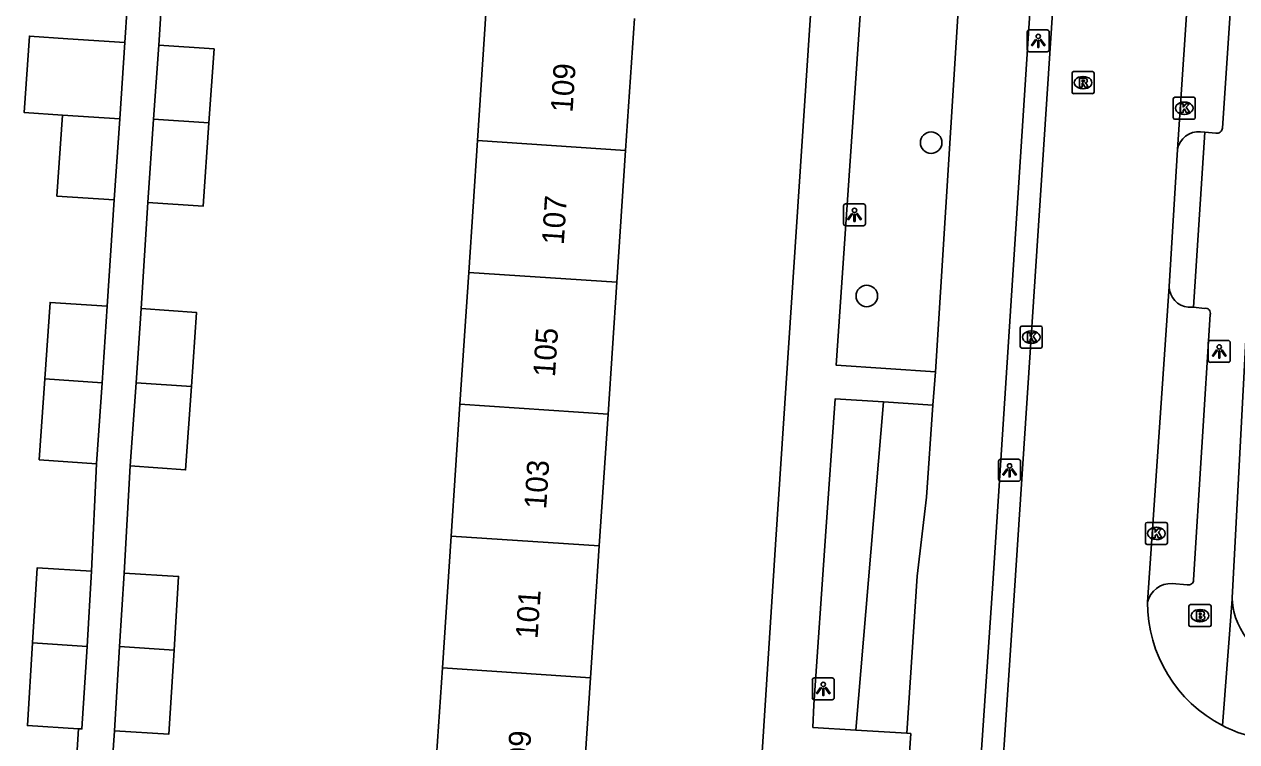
# Model space of a CAD drawing. Extents: x 161848 to 162726, y 385382 to 386521.
# Drawn here: x 162001.6 to 162056.7, y 386169.2 to 386201.9 of the extents above; entities that cross this region are included whole.
import ezdxf

# ---------------------------------------------------------------- set-up
doc = ezdxf.new("R2010")
doc.units = 0
for name, color, linetype in [('IMGEO_Boom', 7, 'Continuous'), ('IMGEO_Brandkraan', 7, 'Continuous'), ('IMGEO_Fietspad_gesloten', 7, 'Continuous'), ('IMGEO_Groenvoorziening', 7, 'Continuous'), ('IMGEO_Kolk', 7, 'Continuous'), ('IMGEO_Lichtpunt', 7, 'Continuous'), ('IMGEO_Pand', 7, 'Continuous'), ('IMGEO_Pand_nummerreeks', 7, 'Continuous'), ('IMGEO_Rijbaan_lokaal_open', 7, 'Continuous'), ('IMGEO_Rioolput', 7, 'Continuous'), ('IMGEO_Voetpad_open', 7, 'Continuous')]:
    doc.layers.add(name, color=color, linetype=linetype)

msp = doc.modelspace()

# ---------------------------------------------------------------- linework, layer by layer
at = {"layer": 'IMGEO_Boom'}
for centre in [(162042.788, 386196.471), (162039.863, 386189.5)]:
    msp.add_circle(centre, 0.489, dxfattribs=at)
at = {"layer": 'IMGEO_Brandkraan'}
for p, q in [((162054.513, 386174.544), (162054.513, 386175.396)), ((162054.588, 386175.47), (162055.44, 386175.47)), ((162055.001, 386175.25), (162055.026, 386175.25)), ((162055.514, 386175.396), (162055.514, 386174.544)), ((162055.44, 386174.47), (162054.588, 386174.47)), ((162055.024, 386174.69), (162054.999, 386174.69))]:
    msp.add_line(p, q, dxfattribs=at)
for points in [[(162054.513, 386174.544), (162054.513, 386175.396)], [(162054.588, 386175.47), (162055.44, 386175.47)], [(162055.514, 386175.396), (162055.514, 386174.544)], [(162054.861, 386175.17), (162054.861, 386174.77), (162055.074, 386174.77)], [(162055.092, 386175.17), (162054.861, 386175.17)], [(162055.04, 386175.089), (162054.986, 386175.089), (162054.986, 386175.013)], [(162054.986, 386175.013), (162055.039, 386175.013)], [(162055.048, 386174.937), (162054.986, 386174.937), (162054.986, 386174.856)], [(162054.986, 386174.856), (162055.048, 386174.856)], [(162055.44, 386174.47), (162054.588, 386174.47)]]:
    msp.add_lwpolyline(points, dxfattribs=at)
for centre, radius, start, end in [((162054.59, 386175.394), 0.0765, 91.552, 178.448), ((162054.59, 386175.394), 0.0765, 91.552, 178.448), ((162055.438, 386175.394), 0.0765, 1.552, 88.448), ((162055.438, 386175.394), 0.0765, 1.552, 88.448), ((162055.041, 386175.051), 0.0379, 267.8285, 90.9355), ((162055.049, 386174.896), 0.0404, 269.8759, 90.5077), ((162055.08, 386175.021), 0.251, 268.6676, 293.5347), ((162055.096, 386175.025), 0.145, 59.4692, 91.5367), ((162055.121, 386175.072), 0.0922, 285.5137, 58.1501), ((162055.126, 386174.88), 0.105, 301.3115, 78.989), ((162054.59, 386174.546), 0.0765, 181.552, 268.448), ((162054.59, 386174.546), 0.0765, 181.552, 268.448), ((162055.438, 386174.546), 0.0765, 271.552, 358.448), ((162055.438, 386174.546), 0.0765, 271.552, 358.448)]:
    msp.add_arc(centre, radius, start, end, dxfattribs=at)
for centre, major_axis, ratio, start_param, end_param in [((162055, 386174.97), (-0.387, 0.002), 0.722429, 4.712389, 7.853982), ((162055.025, 386174.97), (-0.39, 0.002), 0.717154, 1.570796, 4.712389)]:
    msp.add_ellipse(centre, major_axis=major_axis, ratio=ratio, start_param=start_param, end_param=end_param, dxfattribs=at)
at = {"layer": 'IMGEO_Fietspad_gesloten'}
for points in [[(162044.994, 386167.532), (162045.595, 386176.434), (162048.664, 386223.883)], [(162044.15, 386204.652), (162042.986, 386186.047)], [(162042.986, 386186.047), (162042.865, 386184.541)], [(162042.865, 386184.541), (162042.584, 386180.361), (162042.155, 386176.763), (162041.688, 386169.621)], [(162041.688, 386169.621), (162041.864, 386169.606), (162041.762, 386168.083)]]:
    msp.add_lwpolyline(points, dxfattribs=at)
at = {"layer": 'IMGEO_Groenvoorziening'}
msp.add_lwpolyline([(162039.359, 386169.769), (162040.628, 386184.681)], dxfattribs=at)
at = {"layer": 'IMGEO_Kolk'}
for p, q in [((162053.799, 386197.609), (162053.799, 386198.461)), ((162053.874, 386198.535), (162054.726, 386198.535)), ((162054.8, 386198.461), (162054.8, 386197.609)), ((162054.287, 386198.315), (162054.312, 386198.315)), ((162054.726, 386197.535), (162053.874, 386197.535)), ((162054.31, 386197.755), (162054.285, 386197.755)), ((162046.842, 386187.204), (162046.842, 386188.056)), ((162046.917, 386188.13), (162047.769, 386188.13)), ((162047.843, 386188.056), (162047.843, 386187.204)), ((162047.33, 386187.91), (162047.355, 386187.91)), ((162047.769, 386187.13), (162046.917, 386187.13)), ((162047.353, 386187.35), (162047.328, 386187.35)), ((162052.529, 386178.282), (162052.529, 386179.134)), ((162052.604, 386179.208), (162053.456, 386179.208)), ((162053.53, 386179.134), (162053.53, 386178.282)), ((162053.017, 386178.988), (162053.042, 386178.988)), ((162053.456, 386178.208), (162052.604, 386178.208)), ((162053.04, 386178.428), (162053.015, 386178.428))]:
    msp.add_line(p, q, dxfattribs=at)
for points in [[(162053.799, 386197.609), (162053.799, 386198.461)], [(162053.874, 386198.535), (162054.726, 386198.535)], [(162054.8, 386198.461), (162054.8, 386197.609)], [(162054.12, 386198.235), (162054.243, 386198.235), (162054.243, 386198.084), (162054.373, 386198.235), (162054.537, 386198.235), (162054.391, 386198.084), (162054.544, 386197.835), (162054.392, 386197.835), (162054.307, 386197.999), (162054.243, 386197.932), (162054.243, 386197.835), (162054.12, 386197.835), (162054.12, 386198.235)], [(162054.726, 386197.535), (162053.874, 386197.535)], [(162046.842, 386187.204), (162046.842, 386188.056)], [(162046.917, 386188.13), (162047.769, 386188.13)], [(162047.843, 386188.056), (162047.843, 386187.204)], [(162047.163, 386187.83), (162047.286, 386187.83), (162047.286, 386187.679), (162047.416, 386187.83), (162047.58, 386187.83), (162047.434, 386187.679), (162047.587, 386187.43), (162047.435, 386187.43), (162047.35, 386187.594), (162047.286, 386187.527), (162047.286, 386187.43), (162047.163, 386187.43), (162047.163, 386187.83)], [(162047.769, 386187.13), (162046.917, 386187.13)], [(162052.529, 386178.282), (162052.529, 386179.134)], [(162052.604, 386179.208), (162053.456, 386179.208)], [(162053.53, 386179.134), (162053.53, 386178.282)], [(162052.85, 386178.908), (162052.973, 386178.908), (162052.973, 386178.757), (162053.103, 386178.908), (162053.267, 386178.908), (162053.121, 386178.757), (162053.274, 386178.508), (162053.122, 386178.508), (162053.037, 386178.672), (162052.973, 386178.605), (162052.973, 386178.508), (162052.85, 386178.508), (162052.85, 386178.908)], [(162053.456, 386178.208), (162052.604, 386178.208)]]:
    msp.add_lwpolyline(points, dxfattribs=at)
for centre, start, end in [((162053.876, 386198.459), 91.552, 178.448), ((162053.876, 386198.459), 91.552, 178.448), ((162054.724, 386198.459), 1.552, 88.448), ((162054.724, 386198.459), 1.552, 88.448), ((162053.876, 386197.611), 181.552, 268.448), ((162053.876, 386197.611), 181.552, 268.448), ((162054.724, 386197.611), 271.552, 358.448), ((162054.724, 386197.611), 271.552, 358.448), ((162046.919, 386188.054), 91.552, 178.448), ((162046.919, 386188.054), 91.552, 178.448), ((162047.767, 386188.054), 1.552, 88.448), ((162047.767, 386188.054), 1.552, 88.448), ((162046.919, 386187.206), 181.552, 268.448), ((162046.919, 386187.206), 181.552, 268.448), ((162047.767, 386187.206), 271.552, 358.448), ((162047.767, 386187.206), 271.552, 358.448), ((162052.606, 386179.132), 91.552, 178.448), ((162052.606, 386179.132), 91.552, 178.448), ((162053.454, 386179.132), 1.552, 88.448), ((162053.454, 386179.132), 1.552, 88.448), ((162052.606, 386178.284), 181.552, 268.448), ((162052.606, 386178.284), 181.552, 268.448), ((162053.454, 386178.284), 271.552, 358.448), ((162053.454, 386178.284), 271.552, 358.448)]:
    msp.add_arc(centre, 0.0765, start, end, dxfattribs=at)
for centre, major_axis, ratio, start_param, end_param in [((162054.286, 386198.035), (-0.387, 0.002), 0.722429, 4.712389, 7.853982), ((162054.311, 386198.035), (-0.39, 0.002), 0.717154, 1.570796, 4.712389), ((162047.329, 386187.63), (-0.387, 0.002), 0.722429, 4.712389, 7.853982), ((162047.354, 386187.63), (-0.39, 0.002), 0.717154, 1.570796, 4.712389), ((162053.016, 386178.708), (-0.387, 0.002), 0.722429, 4.712389, 7.853982), ((162053.041, 386178.708), (-0.39, 0.002), 0.717154, 1.570796, 4.712389)]:
    msp.add_ellipse(centre, major_axis=major_axis, ratio=ratio, start_param=start_param, end_param=end_param, dxfattribs=at)
at = {"layer": 'IMGEO_Lichtpunt'}
for p, q in [((162047.159, 386201.501), (162047.159, 386200.694)), ((162047.159, 386201.501), (162047.159, 386200.694)), ((162048.061, 386201.596), (162047.253, 386201.596)), ((162048.061, 386201.596), (162047.253, 386201.596)), ((162048.155, 386200.694), (162048.155, 386201.501)), ((162048.155, 386200.694), (162048.155, 386201.501)), ((162047.253, 386200.6), (162048.061, 386200.6)), ((162047.253, 386200.6), (162048.061, 386200.6)), ((162038.804, 386193.592), (162038.804, 386192.785)), ((162038.804, 386193.592), (162038.804, 386192.785)), ((162039.706, 386193.687), (162038.898, 386193.687)), ((162039.706, 386193.687), (162038.898, 386193.687)), ((162039.8, 386192.785), (162039.8, 386193.592)), ((162039.8, 386192.785), (162039.8, 386193.592)), ((162038.898, 386192.691), (162039.706, 386192.691)), ((162038.898, 386192.691), (162039.706, 386192.691)), ((162055.391, 386187.385), (162055.391, 386186.578)), ((162055.391, 386187.385), (162055.391, 386186.578)), ((162056.293, 386187.48), (162055.485, 386187.48)), ((162056.293, 386187.48), (162055.485, 386187.48)), ((162056.387, 386186.578), (162056.387, 386187.385)), ((162056.387, 386186.578), (162056.387, 386187.385)), ((162055.485, 386186.484), (162056.293, 386186.484)), ((162055.485, 386186.484), (162056.293, 386186.484)), ((162045.856, 386181.98), (162045.856, 386181.173)), ((162045.856, 386181.98), (162045.856, 386181.173)), ((162046.758, 386182.075), (162045.95, 386182.075)), ((162046.758, 386182.075), (162045.95, 386182.075)), ((162046.852, 386181.173), (162046.852, 386181.98)), ((162046.852, 386181.173), (162046.852, 386181.98)), ((162045.95, 386181.079), (162046.758, 386181.079)), ((162045.95, 386181.079), (162046.758, 386181.079)), ((162037.386, 386172.046), (162037.386, 386171.239)), ((162037.386, 386172.046), (162037.386, 386171.239)), ((162038.288, 386172.141), (162037.48, 386172.141)), ((162038.288, 386172.141), (162037.48, 386172.141)), ((162038.382, 386171.239), (162038.382, 386172.046)), ((162038.382, 386171.239), (162038.382, 386172.046)), ((162037.48, 386171.145), (162038.288, 386171.145)), ((162037.48, 386171.145), (162038.288, 386171.145))]:
    msp.add_line(p, q, dxfattribs=at)
for points in [[(162047.533, 386201.165), (162047.572, 386201.137), (162047.384, 386200.875), (162047.346, 386200.902), (162047.533, 386201.165)], [(162047.745, 386201.137), (162047.783, 386201.164), (162047.97, 386200.902), (162047.931, 386200.874), (162047.745, 386201.137)], [(162047.635, 386201.117), (162047.682, 386201.117), (162047.682, 386200.795), (162047.635, 386200.795), (162047.635, 386201.117)], [(162039.178, 386193.256), (162039.217, 386193.228), (162039.029, 386192.966), (162038.991, 386192.993), (162039.178, 386193.256)], [(162039.28, 386193.208), (162039.327, 386193.208), (162039.327, 386192.886), (162039.28, 386192.886), (162039.28, 386193.208)], [(162039.39, 386193.228), (162039.428, 386193.255), (162039.615, 386192.993), (162039.576, 386192.965), (162039.39, 386193.228)], [(162055.765, 386187.049), (162055.804, 386187.021), (162055.616, 386186.759), (162055.578, 386186.786), (162055.765, 386187.049)], [(162055.867, 386187.001), (162055.914, 386187.001), (162055.914, 386186.679), (162055.867, 386186.679), (162055.867, 386187.001)], [(162055.977, 386187.021), (162056.015, 386187.048), (162056.202, 386186.786), (162056.163, 386186.758), (162055.977, 386187.021)], [(162046.23, 386181.644), (162046.269, 386181.616), (162046.081, 386181.354), (162046.043, 386181.381), (162046.23, 386181.644)], [(162046.332, 386181.596), (162046.379, 386181.596), (162046.379, 386181.274), (162046.332, 386181.274), (162046.332, 386181.596)], [(162046.442, 386181.616), (162046.48, 386181.643), (162046.667, 386181.381), (162046.628, 386181.353), (162046.442, 386181.616)], [(162037.76, 386171.71), (162037.799, 386171.682), (162037.611, 386171.42), (162037.573, 386171.447), (162037.76, 386171.71)], [(162037.862, 386171.662), (162037.909, 386171.662), (162037.909, 386171.34), (162037.862, 386171.34), (162037.862, 386171.662)], [(162037.972, 386171.682), (162038.01, 386171.709), (162038.197, 386171.447), (162038.158, 386171.419), (162037.972, 386171.682)]]:
    msp.add_lwpolyline(points, dxfattribs=at)
for centre in [(162047.658, 386201.299), (162039.303, 386193.39), (162055.89, 386187.183), (162046.355, 386181.778), (162037.885, 386171.844)]:
    msp.add_circle(centre, 0.0994, dxfattribs=at)
for centre, start, end in [((162047.253, 386201.501), 90, 180), ((162047.253, 386201.501), 90, 180), ((162048.061, 386201.501), 0, 90), ((162048.061, 386201.501), 0, 90), ((162047.253, 386200.694), 180, 270), ((162047.253, 386200.694), 180, 270), ((162048.061, 386200.694), 270, 0), ((162048.061, 386200.694), 270, 360), ((162038.898, 386193.592), 90, 180), ((162038.898, 386193.592), 90, 180), ((162039.706, 386193.592), 0, 90), ((162039.706, 386193.592), 0, 90), ((162038.898, 386192.785), 180, 270), ((162038.898, 386192.785), 180, 270), ((162039.706, 386192.785), 270, 0), ((162039.706, 386192.785), 270, 360), ((162055.485, 386187.385), 90, 180), ((162055.485, 386187.385), 90, 180), ((162056.293, 386187.385), 0, 90), ((162056.293, 386187.385), 0, 90), ((162055.485, 386186.578), 180, 270), ((162055.485, 386186.578), 180, 270), ((162056.293, 386186.578), 270, 0), ((162056.293, 386186.578), 270, 360), ((162045.95, 386181.98), 90, 180), ((162045.95, 386181.98), 90, 180), ((162046.758, 386181.98), 0, 90), ((162046.758, 386181.98), 0, 90), ((162045.95, 386181.173), 180, 270), ((162045.95, 386181.173), 180, 270), ((162046.758, 386181.173), 270, 0), ((162046.758, 386181.173), 270, 360), ((162037.48, 386172.046), 90, 180), ((162037.48, 386172.046), 90, 180), ((162038.288, 386172.046), 0, 90), ((162038.288, 386172.046), 0, 90), ((162037.48, 386171.239), 180, 270), ((162037.48, 386171.239), 180, 270), ((162038.288, 386171.239), 270, 0), ((162038.288, 386171.239), 270, 360)]:
    msp.add_arc(centre, 0.0946, start, end, dxfattribs=at)
at = {"layer": 'IMGEO_Pand'}
for points in [[(162022.558, 386202.552), (162022.159, 386196.56)], [(162028.894, 386196.113), (162029.293, 386202.105)], [(162006.128, 386201.016), (162003.525, 386201.193), (162001.787, 386201.311), (162001.55, 386197.837), (162003.288, 386197.721)], [(162005.891, 386197.547), (162006.128, 386201.016)], [(162007.666, 386200.907), (162007.432, 386197.537)], [(162007.666, 386200.907), (162010.179, 386200.732), (162009.946, 386197.371)], [(162003.288, 386197.721), (162003.037, 386194.04), (162005.64, 386193.863)], [(162003.288, 386197.721), (162005.891, 386197.547)], [(162005.64, 386193.863), (162005.891, 386197.547)], [(162007.432, 386197.537), (162007.17, 386193.755)], [(162009.946, 386197.371), (162009.684, 386193.58), (162007.17, 386193.755)], [(162009.946, 386197.371), (162007.432, 386197.537)], [(162022.159, 386196.56), (162021.76, 386190.569)], [(162022.159, 386196.56), (162028.894, 386196.113)], [(162028.496, 386190.122), (162028.894, 386196.113)], [(162021.362, 386184.577), (162021.76, 386190.569)], [(162021.76, 386190.569), (162028.496, 386190.122)], [(162028.496, 386190.122), (162028.097, 386184.13)], [(162005.325, 386189.029), (162002.722, 386189.206), (162002.485, 386185.732)], [(162005.088, 386185.557), (162005.325, 386189.029)], [(162006.869, 386188.924), (162006.635, 386185.554)], [(162006.869, 386188.924), (162009.382, 386188.749), (162009.149, 386185.388)], [(162002.485, 386185.732), (162002.234, 386182.053), (162004.837, 386181.876)], [(162002.485, 386185.732), (162005.088, 386185.557)], [(162004.837, 386181.876), (162005.088, 386185.557)], [(162006.635, 386185.554), (162006.373, 386181.772)], [(162009.149, 386185.388), (162008.887, 386181.597), (162006.373, 386181.772)], [(162006.635, 386185.554), (162009.149, 386185.388)], [(162020.963, 386178.585), (162021.362, 386184.577)], [(162021.362, 386184.577), (162028.097, 386184.13)], [(162028.097, 386184.13), (162027.698, 386178.138)], [(162020.963, 386178.585), (162020.564, 386172.593)], [(162027.698, 386178.138), (162020.963, 386178.585)], [(162027.299, 386172.146), (162027.698, 386178.138)], [(162004.613, 386176.989), (162002.131, 386177.141), (162001.922, 386173.73)], [(162004.404, 386173.565), (162004.613, 386176.989)], [(162006.086, 386176.907), (162005.881, 386173.567)], [(162006.086, 386176.907), (162008.568, 386176.755), (162008.363, 386173.403)], [(162001.922, 386173.73), (162001.692, 386169.972), (162004.011, 386169.831)], [(162004.404, 386173.565), (162001.922, 386173.73)], [(162004.011, 386169.831), (162004.174, 386169.821), (162004.404, 386173.565)], [(162005.881, 386173.567), (162005.647, 386169.739)], [(162008.363, 386173.403), (162008.13, 386169.587), (162005.647, 386169.739)], [(162008.363, 386173.403), (162005.881, 386173.567)], [(162020.564, 386172.593), (162020.165, 386166.601)], [(162027.299, 386172.146), (162020.564, 386172.593)], [(162026.9, 386166.154), (162027.299, 386172.146)]]:
    msp.add_lwpolyline(points, dxfattribs=at)
at = {"layer": 'IMGEO_Rijbaan_lokaal_open'}
for points in [[(162053.989, 386196.163), (162059.693, 386281.473)], [(162049.721, 386223.815), (162046.601, 386176.338), (162046.003, 386167.514)], [(162053.605, 386189.925), (162053.989, 386196.163)], [(162052.627, 386175.581), (162053.605, 386189.925)]]:
    msp.add_lwpolyline(points, dxfattribs=at)
for centre, radius, start, end in [((162058.921, 386175.568), 6.294, 179.8776, 242.7474), ((162058.919, 386175.565), 6.291, 242.753, 265.0914)]:
    msp.add_arc(centre, radius, start, end, dxfattribs=at)
at = {"layer": 'IMGEO_Rioolput'}
for p, q in [((162049.194, 386198.77), (162049.194, 386199.622)), ((162049.269, 386199.696), (162050.121, 386199.696)), ((162050.195, 386199.622), (162050.195, 386198.77)), ((162049.682, 386199.476), (162049.707, 386199.476)), ((162050.121, 386198.696), (162049.269, 386198.696)), ((162049.705, 386198.916), (162049.68, 386198.916))]:
    msp.add_line(p, q, dxfattribs=at)
for points in [[(162049.194, 386198.77), (162049.194, 386199.622)], [(162049.269, 386199.696), (162050.121, 386199.696)], [(162050.195, 386199.622), (162050.195, 386198.77)], [(162049.783, 386199.394), (162049.531, 386199.396), (162049.531, 386198.996)], [(162049.531, 386198.996), (162049.655, 386198.996), (162049.655, 386199.158), (162049.666, 386199.158)], [(162049.709, 386199.315), (162049.655, 386199.315), (162049.655, 386199.234)], [(162049.655, 386199.234), (162049.707, 386199.234)], [(162049.713, 386199.129), (162049.784, 386198.996), (162049.924, 386198.996), (162049.859, 386199.122)], [(162050.121, 386198.696), (162049.269, 386198.696)]]:
    msp.add_lwpolyline(points, dxfattribs=at)
for centre, radius, start, end in [((162049.271, 386199.62), 0.0765, 91.552, 178.448), ((162049.271, 386199.62), 0.0765, 91.552, 178.448), ((162050.119, 386199.62), 0.0765, 1.552, 88.448), ((162050.119, 386199.62), 0.0765, 1.552, 88.448), ((162049.665, 386199.105), 0.0533, 26.0293, 88.6989), ((162049.691, 386199.423), 0.19, 274.7715, 282.9687), ((162049.715, 386199.219), 0.0964, 77.0061, 93.1865), ((162049.729, 386199.276), 0.0378, 276.6634, 79.6772), ((162049.782, 386199.284), 0.109, 350.3612, 89.416), ((162049.78, 386199.284), 0.112, 277.5842, 350.9817), ((162049.764, 386199.069), 0.108, 29.5134, 73.7905), ((162049.271, 386198.772), 0.0765, 181.552, 268.448), ((162049.271, 386198.772), 0.0765, 181.552, 268.448), ((162050.119, 386198.772), 0.0765, 271.552, 358.448), ((162050.119, 386198.772), 0.0765, 271.552, 358.448)]:
    msp.add_arc(centre, radius, start, end, dxfattribs=at)
for centre, major_axis, ratio, start_param, end_param in [((162049.681, 386199.196), (-0.387, 0.002), 0.722429, 4.712389, 7.853982), ((162049.706, 386199.196), (-0.39, 0.002), 0.717154, 1.570796, 4.712389)]:
    msp.add_ellipse(centre, major_axis=major_axis, ratio=ratio, start_param=start_param, end_param=end_param, dxfattribs=at)
at = {"layer": 'IMGEO_Voetpad_open'}
for points in [[(162061.566, 386280.169), (162056.041, 386197.131)], [(162033.95, 386150.87), (162035.725, 386178.438), (162037.376, 386203.429), (162038.844, 386225.482)], [(162006.443, 386205.851), (162006.128, 386201.016)], [(162007.968, 386205.739), (162007.666, 386200.907)], [(162042.986, 386186.047), (162038.474, 386186.349), (162039.74, 386204.93), (162044.15, 386204.652)], [(162055.234, 386196.94), (162054.716, 386188.99)], [(162055.234, 386196.94), (162055.037, 386196.958)], [(162055.734, 386196.895), (162055.234, 386196.94)], [(162056.49, 386176.046), (162057.463, 386194.369)], [(162005.64, 386193.863), (162005.325, 386189.029)], [(162007.17, 386193.755), (162006.869, 386188.924)], [(162054.482, 386188.988), (162054.716, 386188.99)], [(162054.716, 386188.99), (162055.223, 386188.936)], [(162055.472, 386188.653), (162054.725, 386176.59)], [(162040.628, 386184.681), (162038.422, 386184.819), (162037.977, 386178.576), (162037.461, 386170.909), (162037.41, 386169.892), (162039.359, 386169.769)], [(162042.865, 386184.541), (162040.628, 386184.681)], [(162004.837, 386181.876), (162004.613, 386176.989)], [(162006.373, 386181.772), (162006.086, 386176.907)], [(162054.425, 386176.375), (162053.747, 386176.432)], [(162056.484, 386175.724), (162056.039, 386169.972)], [(162004.011, 386169.831), (162003.72, 386165.053)], [(162005.647, 386169.739), (162005.314, 386164.953)], [(162039.359, 386169.769), (162041.688, 386169.621)]]:
    msp.add_lwpolyline(points, dxfattribs=at)
for centre, radius, start, end in [((162054.945, 386195.991), 0.971, 84.5574, 169.8097), ((162055.771, 386197.165), 0.272, 262.1917, 352.9094), ((162054.589, 386189.967), 0.985, 182.4515, 263.7597), ((162055.274, 386188.73), 0.212, 338.6453, 104.0411), ((162053.709, 386175.319), 1.114, 88.0626, 166.3941), ((162054.49, 386176.601), 0.235, 254.0236, 357.2322), ((162059.726, 386175.825), 3.244, 176.0871, 181.7779), ((162059.558, 386175.834), 3.076, 182.0412, 265.0365)]:
    msp.add_arc(centre, radius, start, end, dxfattribs=at)

# ---------------------------------------------------------------- texts
at = {"layer": 'IMGEO_Pand_nummerreeks'}
for s, p in [('109', (162026.481, 386197.814)), ('107', (162026.081, 386191.805)), ('105', (162025.681, 386185.795)), ('103', (162025.281, 386179.786)), ('101', (162024.889, 386173.89)), ('99', (162024.512, 386168.228))]:
    msp.add_text(s, height=1, rotation=86.192, dxfattribs=at).set_placement(p)

doc.saveas('drawing.dxf')
